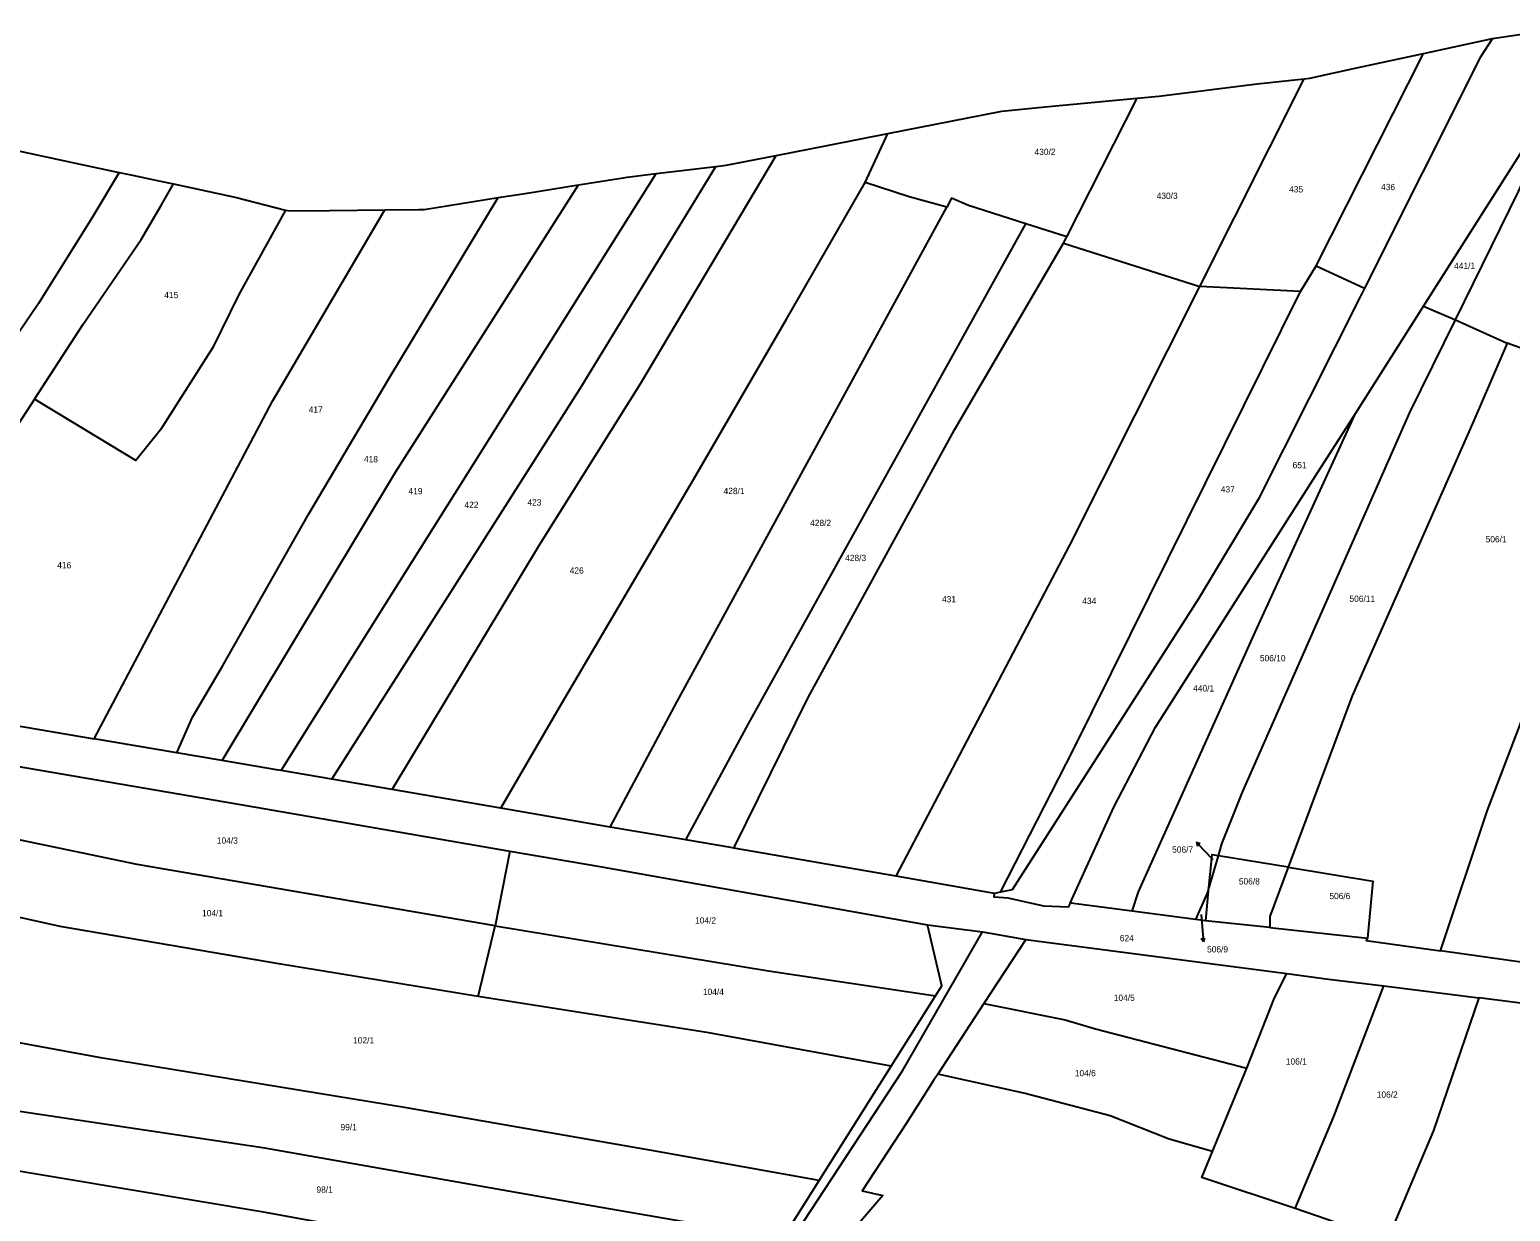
# Model space of a CAD drawing. Extents: x -744566 to -741843, y -1128407 to -1126744.
# Drawn here: x -743441.6 to -743040.3, y -1127178.3 to -1126858 of the extents above; entities that cross this region are included whole.
import ezdxf

# ---------------------------------------------------------------- set-up
doc = ezdxf.new("R2010")
doc.units = 0
for name, color, linetype in [('Hranice parcel', 7, 'Continuous'), ('Parcelní čísla', 7, 'Continuous'), ('Pop  PČ popisy', 7, 'Continuous')]:
    doc.layers.add(name, color=color, linetype=linetype)

msp = doc.modelspace()

# ---------------------------------------------------------------- linework, layer by layer
at = {"layer": 'Hranice parcel'}
for p, q in [((-743045.12, -1126860.39), (-743029.24, -1126857.99)), ((-743063.79, -1126864.46), (-743045.12, -1126860.39)), ((-743092.91, -1126921.98), (-743063.79, -1126864.46)), ((-743124.42, -1126927.65), (-743096.16, -1126871.29)), ((-743160.51, -1126914.13), (-743141.43, -1126876.56)), ((-743215.19, -1126899.42), (-743209.04, -1126886.14)), ((-743271.77, -1126897.03), (-743255.64, -1126895.06)), ((-743160.51, -1126914.13), (-743171.59, -1126910.6)), ((-743161.41, -1126915.91), (-743160.51, -1126914.13)), ((-743161.41, -1126915.91), (-743124.42, -1126927.65)), ((-743097.21, -1126928.95), (-743092.91, -1126921.98)), ((-743092.91, -1126921.98), (-743079.79, -1126928.05)), ((-743097.21, -1126928.95), (-743124.42, -1126927.65)), ((-743079.79, -1126928.05), (-743080.97, -1126930.41)), ((-743082.27, -1126962.07), (-743063.8, -1126932.98)), ((-743063.8, -1126932.98), (-743055.18, -1126936.67)), ((-743055.18, -1126936.67), (-743041.11, -1126943.01)), ((-743030.98, -1126946.66), (-743041.11, -1126943.01)), ((-743401.72, -1127054.05), (-743424.12, -1127050.25)), ((-743389.47, -1127056.13), (-743401.72, -1127054.05)), ((-743359.71, -1127061.21), (-743373.46, -1127058.85)), ((-743343.4, -1127064.01), (-743359.71, -1127061.21)), ((-743313.92, -1127069.06), (-743343.4, -1127064.01)), ((-743284.26, -1127074.14), (-743313.92, -1127069.06)), ((-743311.47, -1127080.65), (-743315.45, -1127100.94)), ((-743206.78, -1127087.5), (-743250.75, -1127079.85)), ((-743122.16, -1127091.42), (-743119.42, -1127081.96)), ((-743100.51, -1127085.04), (-743119.42, -1127081.96)), ((-743180.08, -1127092.14), (-743206.78, -1127087.5)), ((-743122.16, -1127091.42), (-743125.61, -1127099.18)), ((-743122.16, -1127091.42), (-743122.95, -1127099.53)), ((-743178.51, -1127091.81), (-743180.08, -1127092.14)), ((-743125.61, -1127099.18), (-743142.75, -1127096.94)), ((-743122.95, -1127099.53), (-743125.61, -1127099.18)), ((-743105.44, -1127101.41), (-743122.95, -1127099.53)), ((-743320.04, -1127120.06), (-743315.45, -1127100.94)), ((-743198.26, -1127100.66), (-743183.34, -1127102.57)), ((-743105.44, -1127101.41), (-743079.01, -1127104.25)), ((-743171.62, -1127104.6), (-743183.01, -1127122.02)), ((-743171.62, -1127104.6), (-743100.85, -1127113.88)), ((-743074.61, -1127117.23), (-743048.8, -1127120.46)), ((-743208.12, -1127138.99), (-743196.1, -1127119.89)), ((-743183.01, -1127122.02), (-743195.51, -1127141.13)), ((-743227.63, -1127169.97), (-743208.12, -1127138.99)), ((-743121.01, -1127162.08), (-743111.68, -1127139.51)), ((-743237.55, -1127185.73), (-743227.63, -1127169.97))]:
    msp.add_line(p, q, dxfattribs=at)
for points in [[(-743045.12, -1126860.39), (-743048.51, -1126865.51), (-743079.79, -1126928.05)], [(-743096.16, -1126871.29), (-743094.61, -1126871.12), (-743081.5, -1126868.29), (-743066.4, -1126865.02), (-743063.79, -1126864.46)], [(-743063.8, -1126932.98), (-743032.8, -1126884.17), (-743022.51, -1126867.46)], [(-743055.18, -1126936.67), (-743038.05, -1126901.87), (-743022.51, -1126867.46)], [(-743141.43, -1126876.56), (-743135.6, -1126876), (-743108.94, -1126872.71), (-743096.16, -1126871.29)], [(-743209.04, -1126886.14), (-743178.59, -1126880.18), (-743178.08, -1126880.08), (-743166.37, -1126878.96), (-743141.43, -1126876.56)], [(-743500.35, -1126883.98), (-743489.25, -1126884.88), (-743487.94, -1126884.99), (-743474.2, -1126885.91), (-743473.08, -1126885.98), (-743451, -1126889.6), (-743449.81, -1126889.8), (-743427.91, -1126894.47), (-743417.33, -1126896.72)], [(-743239.29, -1126892.07), (-743225.02, -1126889.27), (-743209.04, -1126886.14)], [(-743343.4, -1127064.01), (-743303.47, -1126997.62), (-743275.93, -1126953.86), (-743239.29, -1126892.07)], [(-743255.64, -1126895.06), (-743254.17, -1126894.88), (-743252.8, -1126894.71), (-743239.29, -1126892.07)], [(-743417.33, -1126896.72), (-743424.78, -1126909.13), (-743439.2, -1126932.19), (-743457.17, -1126958.62)], [(-743417.33, -1126896.72), (-743413.79, -1126897.47), (-743406.62, -1126898.99), (-743402.66, -1126899.83)], [(-743373.46, -1127058.85), (-743345.29, -1127013.85), (-743271.77, -1126897.03)], [(-743359.71, -1127061.21), (-743292.37, -1126955.23), (-743255.64, -1126895.06)], [(-743292.9, -1126900.09), (-743280.74, -1126898.16), (-743279.71, -1126898), (-743271.77, -1126897.03)], [(-743440.35, -1126958.18), (-743427.08, -1126937.82), (-743411.38, -1126914.91), (-743405.93, -1126905.47), (-743402.66, -1126899.83)], [(-743402.66, -1126899.83), (-743385.6, -1126903.46), (-743372.24, -1126906.89)], [(-743389.47, -1127056.13), (-743342.45, -1126977.97), (-743292.9, -1126900.09)], [(-743314.63, -1126903.54), (-743307.33, -1126902.38), (-743292.9, -1126900.09)], [(-743313.92, -1127069.06), (-743297.49, -1127040.77), (-743261.68, -1126979.9), (-743236.45, -1126936.5), (-743215.19, -1126899.42)], [(-743193, -1126906.14), (-743203.25, -1126903.35), (-743215.19, -1126899.42)], [(-743372.24, -1126906.89), (-743384.97, -1126929.79), (-743392, -1126944.18), (-743406.19, -1126966.46), (-743412.83, -1126974.8), (-743440.35, -1126958.18)], [(-743424.12, -1127050.25), (-743375.85, -1126958.71), (-743345.39, -1126906.84)], [(-743401.72, -1127054.05), (-743397.47, -1127044.4), (-743389.37, -1127030.54), (-743365.92, -1126989.29), (-743344.18, -1126952.46), (-743314.63, -1126903.54)], [(-743372.24, -1126906.89), (-743371.28, -1126907.14), (-743360.4, -1126907.02), (-743345.39, -1126906.84)], [(-743345.39, -1126906.84), (-743336.16, -1126906.74), (-743334.69, -1126906.72), (-743314.63, -1126903.54)], [(-743284.26, -1127074.14), (-743266.09, -1127040.1), (-743193, -1126906.14)], [(-743171.59, -1126910.6), (-743187.18, -1126905.63), (-743191.74, -1126903.68), (-743193, -1126906.14)], [(-743263.8, -1127077.63), (-743246.71, -1127046.03), (-743171.59, -1126910.6)], [(-743250.75, -1127079.85), (-743230.59, -1127039.01), (-743190.96, -1126966.49), (-743161.41, -1126915.91)], [(-743206.78, -1127087.5), (-743159.7, -1126997.73), (-743124.42, -1126927.65)], [(-743178.51, -1127091.81), (-743158.66, -1127053.1), (-743097.21, -1126928.95)], [(-743080.97, -1126930.41), (-743108.67, -1126985.4), (-743124.8, -1127012.28), (-743175.35, -1127091.16), (-743178.51, -1127091.81)], [(-743119.42, -1127081.96), (-743118.49, -1127078.74), (-743112.93, -1127064.74), (-743067.57, -1126961.77), (-743055.18, -1126936.67)], [(-743041.11, -1126943.01), (-743050.16, -1126963.96), (-743083.16, -1127038.56), (-743100.51, -1127085.04)], [(-743440.35, -1126958.18), (-743461.19, -1126990.18), (-743483.62, -1127023.79)], [(-743159.64, -1127094.74), (-743147.78, -1127068.8), (-743136.47, -1127047.12), (-743093.1, -1126978.92), (-743082.27, -1126962.07)], [(-743142.75, -1127096.94), (-743141.05, -1127091.73), (-743109, -1127020.35), (-743082.27, -1126962.07)], [(-743059.24, -1127107.7), (-743046.52, -1127069.6), (-743031.05, -1127029.12), (-743017.87, -1126995.55), (-743011.05, -1126982.56)], [(-743483.62, -1127023.79), (-743484.09, -1127029.22), (-743483.64, -1127032.8), (-743481.55, -1127036.83), (-743477.98, -1127040.17), (-743473.44, -1127041.87), (-743424.12, -1127050.25)], [(-743505.37, -1127056.75), (-743500.91, -1127053.2), (-743495.43, -1127050.9), (-743489.52, -1127050.44), (-743483.7, -1127051.01), (-743385.04, -1127067.93), (-743311.47, -1127080.65)], [(-743373.46, -1127058.85), (-743374.75, -1127058.63), (-743389.47, -1127056.13)], [(-743315.45, -1127100.94), (-743412.49, -1127084.27), (-743458.97, -1127074.63), (-743478.13, -1127070.26), (-743507.61, -1127059.97)], [(-743263.8, -1127077.63), (-743277.29, -1127075.34), (-743284.26, -1127074.14)], [(-743320.04, -1127120.06), (-743373.57, -1127111.3), (-743433.39, -1127101.15), (-743486.65, -1127089.31), (-743518.91, -1127076.75)], [(-743250.75, -1127079.85), (-743251.53, -1127079.71), (-743263.8, -1127077.63)], [(-743311.47, -1127080.65), (-743287.04, -1127084.88), (-743198.26, -1127100.66)], [(-743119.42, -1127081.96), (-743121.21, -1127081.67), (-743122.16, -1127091.42)], [(-743100.51, -1127085.04), (-743105.49, -1127098.37), (-743105.44, -1127101.41)], [(-743100.51, -1127085.04), (-743077.54, -1127088.79), (-743079.01, -1127104.25)], [(-743159.64, -1127094.74), (-743160.17, -1127095.91), (-743166.78, -1127095.57), (-743176.42, -1127093.47), (-743180.17, -1127093.19), (-743180.08, -1127092.14)], [(-743142.75, -1127096.94), (-743159.38, -1127094.77), (-743159.64, -1127094.74)], [(-743315.45, -1127100.94), (-743241.34, -1127113.11), (-743196.1, -1127119.89)], [(-743280.26, -1127263.68), (-743264.54, -1127233.06), (-743246.95, -1127204.21), (-743235.54, -1127186.77), (-743205.03, -1127140.21), (-743183.34, -1127102.57)], [(-743196.1, -1127119.89), (-743194.38, -1127117.16), (-743198.26, -1127100.66)], [(-743183.34, -1127102.57), (-743182.84, -1127102.64), (-743171.62, -1127104.6)], [(-743227.63, -1127169.97), (-743272.53, -1127161.95), (-743339.46, -1127150.28), (-743422.36, -1127136.74), (-743485.93, -1127125.07), (-743521.87, -1127115.17), (-743538.97, -1127107.07)], [(-743079.01, -1127104.25), (-743079.38, -1127104.87), (-743059.24, -1127107.7)], [(-742996.77, -1127117.36), (-743017.52, -1127113.57), (-743059.24, -1127107.7)], [(-743111.68, -1127139.51), (-743104.19, -1127120.4), (-743100.85, -1127113.88)], [(-743100.85, -1127113.88), (-743089.57, -1127115.36), (-743074.61, -1127117.23)], [(-743098.58, -1127177.58), (-743088.09, -1127152.63), (-743074.61, -1127117.23)], [(-743237.55, -1127185.73), (-743288.76, -1127176.89), (-743377.84, -1127161.22), (-743451.69, -1127150.21), (-743484.81, -1127143.57), (-743511.45, -1127136.91), (-743530.98, -1127131.21), (-743549.04, -1127122.29)], [(-743208.12, -1127138.99), (-743257.58, -1127129.9), (-743320.04, -1127120.06)], [(-743183.01, -1127122.02), (-743160.92, -1127126.4), (-743152.69, -1127128.83), (-743111.68, -1127139.51)], [(-743048.8, -1127120.46), (-743061.12, -1127156.38), (-743073.7, -1127186.12), (-743098.58, -1127177.58)], [(-742989.3, -1127130.42), (-743021.39, -1127124.08), (-743033.19, -1127122.41), (-743048.8, -1127120.46)], [(-743247.25, -1127201.23), (-743341.69, -1127185.22), (-743377.67, -1127178.61), (-743471.09, -1127163.04), (-743495.31, -1127157.9), (-743521.74, -1127151.29), (-743534.96, -1127147.61), (-743558.76, -1127136.98)], [(-743195.51, -1127141.13), (-743196.63, -1127142.85), (-743203.92, -1127154.43), (-743215.95, -1127172.74), (-743210.36, -1127174.02), (-743237.28, -1127205.49), (-743245.75, -1127220.06), (-743259.48, -1127245.93)], [(-743121.01, -1127162.08), (-743132.72, -1127158.77), (-743148.75, -1127152.44), (-743172.16, -1127146.26), (-743195.51, -1127141.13)], [(-743098.58, -1127177.58), (-743123.94, -1127169.17), (-743121.01, -1127162.08)]]:
    msp.add_lwpolyline(points, dxfattribs=at)
at = {"layer": 'Pop  PČ popisy'}
for p, q in [((-743123.35, -1127080.45), (-743125.397, -1127078.255)), ((-743125.397, -1127078.255), (-743124.347, -1127078.646)), ((-743125.397, -1127078.255), (-743125.08, -1127079.329)), ((-743120.87, -1127083.07), (-743123.35, -1127080.45)), ((-743124.1, -1127097.89), (-743123.74, -1127102.32)), ((-743123.74, -1127102.32), (-743123.478, -1127105.31)), ((-743123.478, -1127105.31), (-743124.065, -1127104.356)), ((-743123.478, -1127105.31), (-743123.067, -1127104.268))]:
    msp.add_line(p, q, dxfattribs=at)

# ---------------------------------------------------------------- texts
at = {"layer": 'Parcelní čísla'}
for s, p in [('430/2', (-743169.25, -1126891.98)), ('430/3', (-743136.15, -1126903.89)), ('435', (-743100.25, -1126902.13)), ('436', (-743075.33, -1126901.51)), ('441/1', (-743055.54, -1126922.89)), ('415', (-743405.15, -1126930.78)), ('417', (-743365.99, -1126961.84)), ('418', (-743351.01, -1126975.26)), ('651', (-743099.304, -1126976.88)), ('419', (-743338.93, -1126983.93)), ('428/1', (-743253.54, -1126983.9)), ('437', (-743118.77, -1126983.45)), ('422', (-743323.78, -1126987.67)), ('423', (-743306.71, -1126987)), ('428/2', (-743230.08, -1126992.56)), ('506/1', (-743046.98, -1126996.99)), ('416', (-743434.15, -1127004.02)), ('428/3', (-743220.59, -1127002.06)), ('426', (-743295.25, -1127005.45)), ('506/11', (-743083.89, -1127013.11)), ('431', (-743194.34, -1127013.23)), ('434', (-743156.31, -1127013.7)), ('506/10', (-743108.17, -1127029.22)), ('440/1', (-743126.26, -1127037.41)), ('104/3', (-743390.88, -1127078.65)), ('506/7', (-743131.956, -1127081.103)), ('506/8', (-743113.87, -1127089.72)), ('506/6', (-743089.34, -1127093.69)), ('104/1', (-743394.9, -1127098.32)), ('104/2', (-743261.27, -1127100.3)), ('624', (-743146.144, -1127105.12)), ('506/9', (-743122.49, -1127108.143)), ('104/4', (-743259.14, -1127119.66)), ('104/5', (-743147.78, -1127121.28)), ('102/1', (-743353.96, -1127132.82)), ('106/1', (-743101.14, -1127138.54)), ('104/6', (-743158.34, -1127141.71)), ('106/2', (-743076.5, -1127147.52)), ('99/1', (-743357.37, -1127156.35)), ('98/1', (-743363.89, -1127173.28))]:
    msp.add_text(s, height=1.7, dxfattribs=at).set_placement(p)

doc.saveas('drawing.dxf')
